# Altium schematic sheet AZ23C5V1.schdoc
size 127 x 101 mm
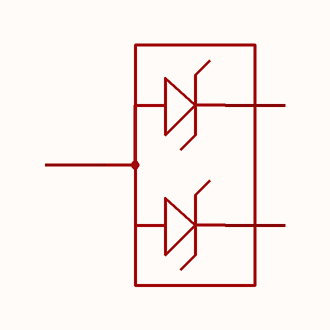
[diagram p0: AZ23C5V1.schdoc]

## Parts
D?  az23c5v1  [SOT-23-3_L2.9-W1.3-P1.90-LS2.4-BR]  (value not drawn)

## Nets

Not connected (* = marked no-connect by the designer): D? 1 2 3

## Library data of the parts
D? = az23c5v1: 二极管配置:1对共阳极;稳压值(标称值):-;稳压值(范围):4.8V~5.4V;耗散功率(Pd):300mW;; Manufacturer: CJ(江苏长电/长晶); AddInBom: yes; ModelId: c62791f0466c4ae2a892c056b845b0ca; ModelName: SOT-23-3P_L2.9-W1.3-H1.0-LS2.4-P0.95; ModelTransform: 98.425,114.173,0,180,0,0,0.0005,-0.0005,0; Diode Configuration: 1对共阳极; Reverse Leakage Current (Ir): 100nA@0.8V; Pd - Power Dissipation: 300mW; Impedance(Zzt): 60Ω; Impedance(Zzk): 480Ω; Operating Junction Temperature Range: -65℃~+150℃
